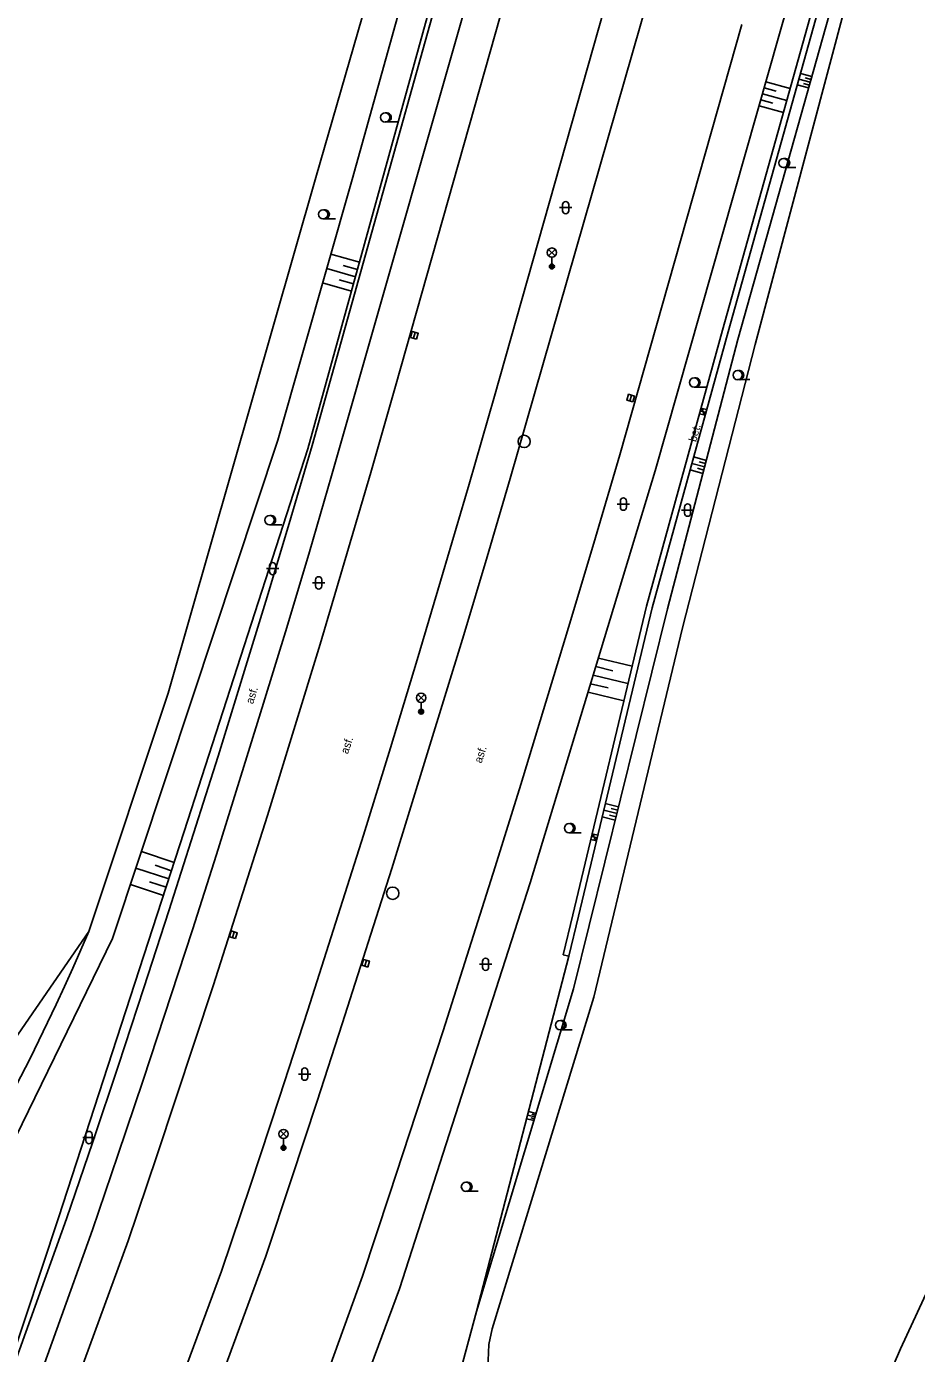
# Model space of a CAD drawing. Extents: x -596024 to -594475, y -1163820 to -1161957.
# Drawn here: x -595600.9 to -595528.6, y -1162806.8 to -1162699 of the extents above; entities that cross this region are included whole.
import ezdxf

# ---------------------------------------------------------------- set-up
doc = ezdxf.new("R2010")
doc.units = 0
for name, color, linetype in [('Level 10', 7, 'Continuous'), ('Level 11', 7, 'Continuous'), ('Level 14', 7, 'Continuous'), ('Level 15', 7, 'Continuous'), ('Level 27', 7, 'Continuous'), ('Level 33', 7, 'Continuous'), ('Level 36', 7, 'Continuous'), ('Level 40', 7, 'Continuous')]:
    doc.layers.add(name, color=color, linetype=linetype)

msp = doc.modelspace()

# ---------------------------------------------------------------- linework, layer by layer
at = {"layer": 'Level 10'}
for points in [[(-595570.89, -1162728.27), (-595561.92, -1162696.58), (-595554.03, -1162668.87), (-595542.67, -1162628.44), (-595540.22, -1162619.73)], [(-595532.72, -1162622.29), (-595535.2, -1162631.1), (-595546.35, -1162670.84), (-595562.86, -1162729.06)], [(-595561.58, -1162735.76), (-595550.96, -1162698.83), (-595543.31, -1162671.66), (-595532.16, -1162632.1), (-595529.7, -1162623.31)], [(-595552.67, -1162733.84), (-595542.76, -1162698.87)], [(-595592.61, -1162797.68), (-595590.27, -1162790.79), (-595585.7, -1162776.98), (-595581.28, -1162763.12), (-595577.01, -1162749.22), (-595572.89, -1162735.26), (-595570.89, -1162728.27)], [(-595562.86, -1162729.06), (-595564.92, -1162736.22), (-595567.01, -1162743.36), (-595569.13, -1162750.5), (-595571.3, -1162757.63), (-595573.5, -1162764.74), (-595578, -1162778.94), (-595580.31, -1162786.01), (-595582.65, -1162793.08), (-595585.03, -1162800.14)], [(-595552.67, -1162733.84), (-595554.64, -1162740.55), (-595556.64, -1162747.25), (-595558.67, -1162753.94), (-595560.72, -1162760.62), (-595562.8, -1162767.3), (-595567.03, -1162780.63), (-595571.37, -1162793.93), (-595573.57, -1162800.56)], [(-595581.43, -1162798.92), (-595579.33, -1162792.64), (-595577.26, -1162786.35), (-595575.21, -1162780.06), (-595571.19, -1162767.44), (-595565.35, -1162748.46), (-595563.45, -1162742.11), (-595561.58, -1162735.76)], [(-595601.5, -1162822.03), (-595592.61, -1162797.68)], [(-595595.81, -1162837.87), (-595594.84, -1162835.47), (-595581.43, -1162798.92)], [(-595585.03, -1162800.14), (-595597.68, -1162834.31), (-595598.67, -1162836.74)], [(-595584.54, -1162830.89), (-595573.57, -1162800.56)]]:
    msp.add_lwpolyline(points, dxfattribs=at)
at = {"layer": 'Level 11'}
for points in [[(-595595.79, -1162772.55), (-595589.35, -1162753.19), (-595577.35, -1162711.3), (-595568.12, -1162679.34), (-595552.22, -1162632.76), (-595547.96, -1162617.09)], [(-595545.2, -1162618.03), (-595548.02, -1162628.22), (-595558.9, -1162667.45), (-595565.42, -1162689.3), (-595577.65, -1162733.09)], [(-595576.08, -1162735.54), (-595563.22, -1162690.47), (-595556.98, -1162668.04), (-595545.95, -1162628.43), (-595543.19, -1162618.72)], [(-595532.75, -1162691.29), (-595541.67, -1162724.87), (-595547.57, -1162747.9), (-595554.79, -1162777.89), (-595563.05, -1162804.83)], [(-595535.02, -1162690.4), (-595544.34, -1162723.71)], [(-595534.56, -1162690.53), (-595543.88, -1162723.84)], [(-595544.34, -1162723.71), (-595550.51, -1162746.14)], [(-595543.88, -1162723.84), (-595550.05, -1162746.26)], [(-595597.6, -1162795.89), (-595595.48, -1162789.65), (-595593.39, -1162783.4), (-595591.33, -1162777.14), (-595589.29, -1162770.87), (-595587.29, -1162764.6), (-595585.3, -1162758.31), (-595581.42, -1162745.72), (-595579.52, -1162739.41), (-595577.65, -1162733.09)], [(-595576.08, -1162735.54), (-595577.89, -1162741.71), (-595579.73, -1162747.87), (-595581.6, -1162754.01), (-595585.43, -1162766.29), (-595587.38, -1162772.41), (-595591.39, -1162784.62), (-595593.44, -1162790.72), (-595595.51, -1162796.8)], [(-595550.51, -1162746.14), (-595556.49, -1162771.19)], [(-595550.05, -1162746.26), (-595556.03, -1162771.3)], [(-595556.49, -1162771.19), (-595557.27, -1162774.46)], [(-595556.03, -1162771.3), (-595556.81, -1162774.57)], [(-595614.19, -1162799.22), (-595595.79, -1162772.55)], [(-595557.27, -1162774.46), (-595556.81, -1162774.57)], [(-595544.62, -1162820.66), (-595543.63, -1162820.87), (-595541.62, -1162821.03), (-595539.62, -1162820.86), (-595538.63, -1162820.65), (-595537.67, -1162820.35), (-595536.73, -1162819.97), (-595534.97, -1162818.99), (-595533.36, -1162814.77), (-595531.66, -1162810.6), (-595529.87, -1162806.46), (-595527.98, -1162802.36), (-595526.01, -1162798.3), (-595523.95, -1162794.28), (-595521.8, -1162790.32), (-595519.56, -1162786.4), (-595517.24, -1162782.53), (-595514.84, -1162778.71)], [(-595606.4, -1162820.34), (-595597.6, -1162795.89)], [(-595601.5, -1162822.03), (-595604.23, -1162820.98), (-595595.51, -1162796.8)], [(-595563.05, -1162804.83), (-595563.3, -1162806.1), (-595563.37, -1162807.4), (-595563.24, -1162808.69), (-595562.93, -1162809.95), (-595562.44, -1162811.15), (-595561.77, -1162812.26), (-595560.96, -1162813.27), (-595560, -1162814.15), (-595558.93, -1162814.88), (-595557.76, -1162815.44)]]:
    msp.add_lwpolyline(points, dxfattribs=at)
msp.add_arc((-595760.93, -1162702.32), 179.45, 320.3685, 336.9602, dxfattribs=at)
at = {"layer": 'Level 14'}
for points in [[(-595574.41, -1162711.48), (-595565.74, -1162680.38)], [(-595539.69, -1162699.63), (-595535.17, -1162683.87)], [(-595533.63, -1162690.86), (-595543.08, -1162724.47)], [(-595578, -1162733.34), (-595566.82, -1162692.87)], [(-595549.79, -1162735.15), (-595539.69, -1162699.63)], [(-595580.46, -1162732.65), (-595574.41, -1162711.48)], [(-595543.08, -1162724.47), (-595548.79, -1162746.35)], [(-595588.05, -1162764.44), (-595578, -1162733.34)], [(-595587.37, -1162753.54), (-595580.46, -1162732.65)], [(-595559.96, -1162768.61), (-595549.79, -1162735.15)], [(-595548.79, -1162746.35), (-595556.43, -1162777.22)], [(-595593.87, -1162773.13), (-595587.37, -1162753.54)], [(-595598.26, -1162795.82), (-595588.05, -1162764.44)], [(-595570.57, -1162801.58), (-595559.96, -1162768.61)], [(-595610.17, -1162806.51), (-595593.87, -1162773.13)], [(-595556.81, -1162774.57), (-595564.3, -1162803.42)], [(-595556.43, -1162777.22), (-595564.3, -1162803.42)], [(-595606.4, -1162820.34), (-595598.26, -1162795.82)], [(-595581.85, -1162832.04), (-595570.57, -1162801.58)], [(-595564.3, -1162803.42), (-595568.78, -1162819.98)]]:
    msp.add_lwpolyline(points, dxfattribs=at)
at = {"layer": 'Level 15'}
for points in [[(-595538.01, -1162702.85), (-595537.07, -1162703.11)], [(-595539.96, -1162704.29), (-595540.94, -1162704.02)], [(-595538.84, -1162704.08), (-595540.8, -1162703.53)], [(-595538.27, -1162703.78), (-595537.34, -1162704.04)], [(-595538.14, -1162703.31), (-595537.21, -1162703.58)], [(-595537.74, -1162703.68), (-595537.27, -1162703.81)], [(-595537.61, -1162703.21), (-595537.14, -1162703.34)], [(-595540.24, -1162705.27), (-595541.22, -1162705)], [(-595539.12, -1162705.05), (-595541.08, -1162704.51)], [(-595539.39, -1162706.03), (-595541.35, -1162705.48)], [(-595576.14, -1162717.54), (-595573.82, -1162718.2)], [(-595576.48, -1162718.7), (-595574.14, -1162719.37)], [(-595575.14, -1162718.45), (-595573.98, -1162718.79)], [(-595576.81, -1162719.87), (-595574.46, -1162720.54)], [(-595575.47, -1162719.62), (-595574.3, -1162719.96)], [(-595546.08, -1162730.04), (-595545.62, -1162730.16)], [(-595546.21, -1162730.5), (-595545.75, -1162730.62)], [(-595546.14, -1162730.27), (-595545.68, -1162730.39)], [(-595545.88, -1162730.22), (-595546.11, -1162730.15)], [(-595545.94, -1162730.45), (-595545.72, -1162730.51)], [(-595546.68, -1162734.01), (-595545.64, -1162734.29)], [(-595546.23, -1162734.41), (-595545.71, -1162734.55)], [(-595546.97, -1162735.05), (-595545.92, -1162735.34)], [(-595546.82, -1162734.53), (-595545.78, -1162734.82)], [(-595546.37, -1162734.93), (-595545.85, -1162735.08)], [(-595551.67, -1162751), (-595554.41, -1162750.35)], [(-595553.23, -1162751.37), (-595554.62, -1162751.04)], [(-595553.61, -1162752.77), (-595555.04, -1162752.43)], [(-595552.01, -1162752.41), (-595554.83, -1162751.74)], [(-595552.34, -1162753.82), (-595555.25, -1162753.12)], [(-595553.85, -1162762.17), (-595552.77, -1162762.43)], [(-595554.11, -1162763.25), (-595553.04, -1162763.5)], [(-595553.98, -1162762.71), (-595552.9, -1162762.97)], [(-595553.51, -1162763.11), (-595552.97, -1162763.24)], [(-595553.38, -1162762.57), (-595552.84, -1162762.7)], [(-595555.03, -1162765.07), (-595554.57, -1162765.18)], [(-595554.98, -1162764.84), (-595554.51, -1162764.95)], [(-595554.72, -1162764.78), (-595554.95, -1162764.72)], [(-595554.92, -1162764.61), (-595554.46, -1162764.72)], [(-595554.77, -1162765.01), (-595554.54, -1162765.07)], [(-595591.53, -1162766.07), (-595588.87, -1162766.96)], [(-595591.98, -1162767.41), (-595589.3, -1162768.29)], [(-595590.42, -1162767.18), (-595589.09, -1162767.63)], [(-595592.42, -1162768.74), (-595589.74, -1162769.63)], [(-595590.86, -1162768.52), (-595589.52, -1162768.96)], [(-595560.08, -1162787.17), (-595559.47, -1162787.33)], [(-595560.24, -1162787.77), (-595559.64, -1162787.92)], [(-595560.16, -1162787.47), (-595559.56, -1162787.62)], [(-595559.9, -1162787.7), (-595559.6, -1162787.77)], [(-595559.81, -1162787.4), (-595559.51, -1162787.47)]]:
    msp.add_lwpolyline(points, dxfattribs=at)
at = {"layer": 'Level 27'}
for p, q in [((-595569.43, -1162724.37), (-595569.29, -1162723.89)), ((-595551.86, -1162729.47), (-595551.72, -1162728.99)), ((-595584.13, -1162773.06), (-595583.99, -1162772.58)), ((-595573.39, -1162775.37), (-595573.25, -1162774.89))]:
    msp.add_line(p, q, dxfattribs=at)
for points in [[(-595569.19, -1162724.44), (-595569.05, -1162723.96), (-595569.53, -1162723.82), (-595569.67, -1162724.3)], [(-595551.62, -1162729.54), (-595551.48, -1162729.06), (-595551.96, -1162728.92), (-595552.1, -1162729.4)], [(-595583.89, -1162773.13), (-595583.75, -1162772.65), (-595584.23, -1162772.51), (-595584.37, -1162772.99)], [(-595573.15, -1162775.44), (-595573.01, -1162774.96), (-595573.49, -1162774.82), (-595573.63, -1162775.3)]]:
    msp.add_lwpolyline(points, close=True, dxfattribs=at)
for centre in [(-595560.44, -1162732.75), (-595571.12, -1162769.45)]:
    msp.add_circle(centre, 0.5, dxfattribs=at)
at = {"layer": 'Level 33'}
for p, q in [((-595558.46, -1162717.68), (-595557.93, -1162717.15)), ((-595558.46, -1162717.15), (-595557.93, -1162717.68)), ((-595558.19, -1162717.79), (-595558.19, -1162718.54)), ((-595569.07, -1162753.84), (-595568.54, -1162753.31)), ((-595569.07, -1162753.31), (-595568.54, -1162753.84)), ((-595568.81, -1162753.95), (-595568.81, -1162754.7)), ((-595580.25, -1162789.26), (-595579.72, -1162788.73)), ((-595580.25, -1162788.73), (-595579.72, -1162789.26)), ((-595579.99, -1162789.37), (-595579.99, -1162790.12))]:
    msp.add_line(p, q, dxfattribs=at)
for centre, radius in [((-595558.19, -1162717.41), 0.375), ((-595558.19, -1162718.54), 0.2), ((-595558.19, -1162718.54), 0.145), ((-595558.19, -1162718.54), 0.0876), ((-595568.81, -1162753.57), 0.375), ((-595568.81, -1162754.7), 0.2), ((-595568.81, -1162754.7), 0.145), ((-595568.81, -1162754.7), 0.0876), ((-595579.99, -1162789), 0.375), ((-595579.99, -1162790.12), 0.2), ((-595579.99, -1162790.12), 0.145), ((-595579.99, -1162790.12), 0.0876)]:
    msp.add_circle(centre, radius, dxfattribs=at)
at = {"layer": 'Level 36'}
for p, q in [((-595571.73, -1162706.8), (-595570.73, -1162706.8)), ((-595539.38, -1162710.5), (-595538.38, -1162710.5)), ((-595557.57, -1162713.76), (-595556.57, -1162713.76)), ((-595557.32, -1162713.51), (-595557.32, -1162714.01)), ((-595556.82, -1162713.51), (-595556.82, -1162714.01)), ((-595576.77, -1162714.68), (-595575.77, -1162714.68)), ((-595543.1, -1162727.73), (-595542.1, -1162727.73)), ((-595546.64, -1162728.34), (-595545.64, -1162728.34)), ((-595552.63, -1162737.59), (-595552.63, -1162738.09)), ((-595552.13, -1162737.59), (-595552.13, -1162738.09)), ((-595552.88, -1162737.84), (-595551.88, -1162737.84)), ((-595547.67, -1162738.33), (-595546.67, -1162738.33)), ((-595547.42, -1162738.08), (-595547.42, -1162738.58)), ((-595546.92, -1162738.08), (-595546.92, -1162738.58)), ((-595581.12, -1162739.52), (-595580.12, -1162739.52)), ((-595581.12, -1162742.83), (-595581.12, -1162743.33)), ((-595580.62, -1162742.83), (-595580.62, -1162743.33)), ((-595581.37, -1162743.08), (-595580.37, -1162743.08)), ((-595577.38, -1162743.99), (-595577.38, -1162744.49)), ((-595576.88, -1162743.99), (-595576.88, -1162744.49)), ((-595577.63, -1162744.24), (-595576.63, -1162744.24)), ((-595556.8, -1162764.53), (-595555.8, -1162764.53)), ((-595564.08, -1162775.22), (-595563.08, -1162775.22)), ((-595563.83, -1162774.97), (-595563.83, -1162775.47)), ((-595563.33, -1162774.97), (-595563.33, -1162775.47)), ((-595557.53, -1162780.53), (-595556.53, -1162780.53)), ((-595578.51, -1162783.89), (-595578.51, -1162784.39)), ((-595578.01, -1162783.89), (-595578.01, -1162784.39)), ((-595578.76, -1162784.14), (-595577.76, -1162784.14)), ((-595596.29, -1162789.29), (-595595.29, -1162789.29)), ((-595596.04, -1162789.04), (-595596.04, -1162789.54)), ((-595595.54, -1162789.04), (-595595.54, -1162789.54)), ((-595565.17, -1162793.66), (-595564.17, -1162793.66))]:
    msp.add_line(p, q, dxfattribs=at)
for centre in [(-595571.73, -1162706.43), (-595539.38, -1162710.13), (-595576.77, -1162714.3), (-595546.64, -1162727.96), (-595543.1, -1162727.36), (-595581.12, -1162739.14), (-595556.8, -1162764.16), (-595557.53, -1162780.16), (-595565.17, -1162793.29)]:
    msp.add_circle(centre, 0.375, dxfattribs=at)
for centre, radius, start, end in [((-595571.61, -1162706.43), 0.375, 260.4059, 99.5941), ((-595539.25, -1162710.13), 0.375, 260.4059, 99.5941), ((-595576.64, -1162714.3), 0.375, 260.4059, 99.5941), ((-595557.07, -1162713.51), 0.25, 0, 180), ((-595557.07, -1162714.01), 0.25, 180, 0), ((-595546.52, -1162727.96), 0.375, 260.4059, 99.5941), ((-595542.98, -1162727.36), 0.375, 260.4059, 99.5941), ((-595552.38, -1162737.59), 0.25, 0, 180), ((-595552.38, -1162738.09), 0.25, 180, 0), ((-595547.17, -1162738.08), 0.25, 0, 180), ((-595547.17, -1162738.58), 0.25, 180, 0), ((-595581, -1162739.14), 0.375, 260.4059, 99.5941), ((-595580.87, -1162742.83), 0.25, 0, 180), ((-595580.87, -1162743.33), 0.25, 180, 0), ((-595577.13, -1162743.99), 0.25, 0, 180), ((-595577.13, -1162744.49), 0.25, 180, 0), ((-595556.68, -1162764.16), 0.375, 260.4059, 99.5941), ((-595563.58, -1162774.97), 0.25, 0, 180), ((-595563.58, -1162775.47), 0.25, 180, 0), ((-595557.41, -1162780.16), 0.375, 260.4059, 99.5941), ((-595578.26, -1162783.89), 0.25, 0, 180), ((-595578.26, -1162784.39), 0.25, 180, 0), ((-595595.79, -1162789.04), 0.25, 0, 180), ((-595595.79, -1162789.54), 0.25, 180, 0), ((-595565.05, -1162793.29), 0.375, 260.4059, 99.5941)]:
    msp.add_arc(centre, radius, start, end, dxfattribs=at)

# ---------------------------------------------------------------- texts
at = {"layer": 'Level 40'}
for s, rotation, p in [('bet.', 74.6196, (-595546.47, -1162732.83)), ('asf.', 73.2, (-595582.46, -1162754.12)), ('asf.', 71.41, (-595574.76, -1162758.18)), ('asf.', 71.41, (-595563.91, -1162758.93))]:
    msp.add_text(s, height=0.65, rotation=rotation, dxfattribs=at).set_placement(p)

doc.saveas('drawing.dxf')
